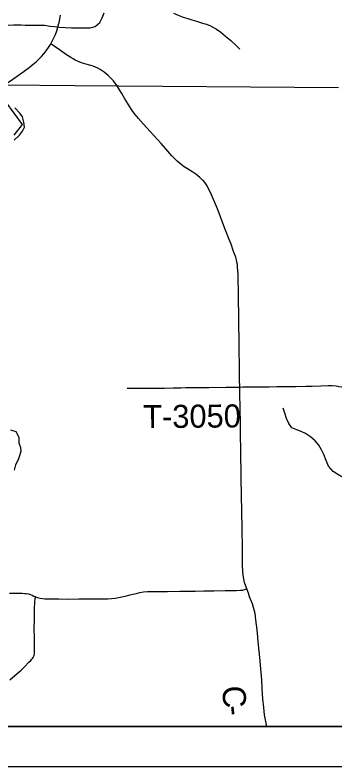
# Model space of a CAD drawing. Extents: x 0 to 34, y 0 to 22.
# Drawn here: x 3.328 to 4.117, y 14.287 to 16.14 of the extents above; entities that cross this region are included whole.
import ezdxf

# ---------------------------------------------------------------- set-up
doc = ezdxf.new("R2010")
doc.units = 0
for name, color, linetype in [('GM_X_County_Road', 7, 'Continuous'), ('GM_X_County_Road_Text', 7, 'Continuous'), ('GM_X_Interchange_Ramps', 7, 'Continuous'), ('GM_X_Section_Text', 7, 'Continuous'), ('GM_X_State_Route', 7, 'Continuous'), ('GM_X_State_Shield', 7, 'Continuous'), ('GM_X_Township_Road', 7, 'Continuous'), ('GM_X_Township_Text', 7, 'Continuous'), ('SH_Data', 7, 'Continuous')]:
    doc.layers.add(name, color=color, linetype=linetype)

msp = doc.modelspace()

# ---------------------------------------------------------------- linework, layer by layer
at = {"layer": 'GM_X_County_Road'}
msp.add_lwpolyline([(3.3022, 15.9674), (3.3093, 15.9728), (3.3228, 15.9822), (3.3508, 16.0019), (3.3633, 16.0111), (3.373, 16.0188), (3.38, 16.0248), (3.3868, 16.0312), (3.3933, 16.0378), (3.3995, 16.0447), (3.4052, 16.052), (3.4106, 16.0596), (3.4156, 16.0674), (3.4164, 16.0689), (3.4201, 16.0755), (3.4242, 16.0838), (3.4279, 16.0923), (3.4312, 16.101), (3.4341, 16.1098), (3.4365, 16.1188), (3.4378, 16.1248), (3.4389, 16.1309), (3.4401, 16.1401)], dxfattribs=at)
at = {"layer": 'GM_X_County_Road_Text'}
for points in [[(3.2957, 16.1168), (3.3124, 16.1151), (3.3242, 16.1155), (3.3435, 16.1156), (3.353, 16.1153), (3.3901, 16.1154), (3.4011, 16.1147), (3.4151, 16.1128), (3.4254, 16.1114), (3.4367, 16.1099), (3.4519, 16.1092), (3.4678, 16.1085), (3.4936, 16.1086), (3.5035, 16.1082), (3.5133, 16.1087), (3.5254, 16.1121), (3.5375, 16.1213), (3.5431, 16.1334), (3.5476, 16.1452)], [(3.7185, 16.1447), (3.7307, 16.1398), (3.7428, 16.1346), (3.7542, 16.1316), (3.7641, 16.1282), (3.7755, 16.1252), (3.7903, 16.12), (3.8001, 16.1173), (3.81, 16.1136), (3.8248, 16.1053), (3.8355, 16.0977), (3.8473, 16.0879), (3.8598, 16.0773), (3.8731, 16.0652), (3.8826, 16.0562)], [(4.1378, 14.9976), (4.1377, 14.9995), (4.124, 15.0077), (4.1122, 15.0152), (4.1011, 15.028), (4.0953, 15.042), (4.0891, 15.0564), (4.0836, 15.0681), (4.0767, 15.0794), (4.0683, 15.0907), (4.0564, 15.1005), (4.0442, 15.1083), (4.0336, 15.1131), (4.0229, 15.1172), (4.0107, 15.1228), (4.003, 15.1334), (3.9973, 15.1454), (3.993, 15.1587), (3.9891, 15.1708)], [(3.3172, 15.1172), (3.3305, 15.1131), (3.3374, 15.0995), (3.3376, 15.0855), (3.3418, 15.0741), (3.3427, 15.0647), (3.3394, 15.0536), (3.3357, 15.0437), (3.3297, 15.0312), (3.3257, 15.0182)]]:
    msp.add_lwpolyline(points, dxfattribs=at)
at = {"layer": 'GM_X_Interchange_Ramps'}
for points in [[(3.6044, 15.2203), (3.6437, 15.2202), (3.678, 15.2203), (3.6967, 15.2204), (3.7184, 15.2209), (3.7371, 15.2215), (3.7496, 15.2216), (3.7813, 15.2216), (3.8059, 15.222), (3.849, 15.2224), (3.8707, 15.2228), (3.882, 15.2231)], [(3.882, 15.2231), (3.8894, 15.2232), (3.9019, 15.2234), (3.9174, 15.2236), (3.936, 15.2238), (3.9547, 15.2239), (3.9733, 15.2241), (3.9982, 15.2243), (4.02, 15.2246), (4.0449, 15.2252), (4.0604, 15.2255), (4.0822, 15.2263), (4.1009, 15.2268), (4.1102, 15.2267), (4.1195, 15.2259), (4.1266, 15.2248), (4.1333, 15.2232), (4.1402, 15.2211)], [(3.3794, 14.7059), (3.3839, 14.7043), (3.3898, 14.7027), (3.3959, 14.7017), (3.402, 14.7011), (3.4174, 14.7007), (3.436, 14.7007), (3.4609, 14.7006), (3.4858, 14.7008), (3.5044, 14.7009), (3.5168, 14.7009), (3.5364, 14.7008), (3.557, 14.7013), (3.5662, 14.7018), (3.5754, 14.7028), (3.5876, 14.7049), (3.5997, 14.7076), (3.6118, 14.7106), (3.6298, 14.7153), (3.636, 14.7166), (3.6452, 14.718), (3.6545, 14.7188), (3.67, 14.7192), (3.6886, 14.7193), (3.704, 14.7193), (3.7348, 14.7196), (3.7502, 14.7199), (3.7719, 14.7202), (3.7936, 14.7205), (3.8184, 14.7209), (3.8464, 14.7212), (3.8744, 14.7216), (3.8837, 14.722), (3.8895, 14.7228), (3.8936, 14.7237), (3.8966, 14.7245), (3.8997, 14.7256)], [(3.3148, 14.7149), (3.3344, 14.7149), (3.3456, 14.7147), (3.3513, 14.7144), (3.3557, 14.7141), (3.3616, 14.7134), (3.3667, 14.7118), (3.3705, 14.7103), (3.3747, 14.7079), (3.3794, 14.7059)], [(3.3151, 14.5014), (3.3339, 14.5169), (3.343, 14.5251), (3.3519, 14.5337), (3.3625, 14.545), (3.367, 14.5493), (3.3691, 14.5515), (3.3712, 14.554), (3.3731, 14.5567), (3.3746, 14.5594), (3.3755, 14.5622), (3.3762, 14.5651), (3.3765, 14.5714), (3.3765, 14.5807), (3.3761, 14.6055), (3.3757, 14.6273), (3.3759, 14.649), (3.3764, 14.68), (3.3768, 14.6893), (3.3771, 14.6955), (3.3776, 14.6987), (3.3782, 14.7018), (3.3794, 14.7059)]]:
    msp.add_lwpolyline(points, dxfattribs=at)
at = {"layer": 'GM_X_State_Route'}
for points in [[(4.1201, 16.507), (4.1149, 16.7255), (3.8667, 16.7261), (3.8624, 16.726), (3.8538, 16.7259), (3.7775, 16.7251), (3.6944, 16.7259), (3.6091, 16.7254), (3.5492, 16.7252), (3.5064, 16.7242), (3.4642, 16.7247), (3.3781, 16.7258), (3.3363, 16.7271), (3.2929, 16.7282), (3.2508, 16.7281), (3.0563, 16.7255), (2.994, 16.7266), (1.8602, 16.7212), (1.8602, 14.3866), (4.1451, 14.3866)], [(3.302, 15.9679), (3.4757, 15.9666), (4.1252, 15.961)], [(3.3259, 15.8442), (3.3468, 15.8704), (3.2842, 15.9538)]]:
    msp.add_lwpolyline(points, dxfattribs=at)
at = {"layer": 'GM_X_State_Shield'}
msp.add_lwpolyline([(3.3265, 15.8313), (3.339, 15.8439), (3.3465, 15.8538), (3.3514, 15.8633), (3.3502, 15.8758), (3.3464, 15.8887), (3.3399, 15.8985), (3.3281, 15.9114)], dxfattribs=at)
at = {"layer": 'GM_X_Township_Road'}
for points in [[(3.5812, 15.9639), (3.5784, 15.9682), (3.5746, 15.9731), (3.5706, 15.9777), (3.5641, 15.9844), (3.5574, 15.9909), (3.5528, 15.9949), (3.5479, 15.9988), (3.5429, 16.0024), (3.5377, 16.0058), (3.5324, 16.0088), (3.5268, 16.0115), (3.5211, 16.0138), (3.5152, 16.0158), (3.5063, 16.0184), (3.4942, 16.0217), (3.4883, 16.0237), (3.4824, 16.026), (3.4767, 16.0287), (3.4712, 16.0317), (3.4659, 16.035), (3.4529, 16.0437), (3.44, 16.0525), (3.427, 16.0613), (3.4245, 16.0631), (3.4164, 16.0689)], [(3.882, 15.2231), (3.8817, 15.242), (3.8816, 15.2669), (3.8814, 15.2793), (3.881, 15.3104), (3.8808, 15.3291), (3.8805, 15.3478), (3.8801, 15.3695), (3.8798, 15.385), (3.8796, 15.4099), (3.8794, 15.4286), (3.8788, 15.4628), (3.8785, 15.4846), (3.8781, 15.5002), (3.8777, 15.5094), (3.8769, 15.5187), (3.8762, 15.5248), (3.8751, 15.5309), (3.8738, 15.5369), (3.8721, 15.5428), (3.867, 15.5575), (3.8606, 15.5751), (3.8563, 15.5867), (3.8473, 15.6099), (3.8404, 15.6273), (3.8336, 15.6447), (3.8269, 15.6621), (3.82, 15.6794), (3.8152, 15.6909), (3.81, 15.7022), (3.8045, 15.7133), (3.8015, 15.7187), (3.7982, 15.7239), (3.7965, 15.7264), (3.7926, 15.7312), (3.7905, 15.7334), (3.7838, 15.7399), (3.7791, 15.7439), (3.7742, 15.7476), (3.7665, 15.7528), (3.7533, 15.761), (3.7454, 15.766), (3.7378, 15.7715), (3.7329, 15.7754), (3.7282, 15.7795), (3.7215, 15.7861), (3.7151, 15.7929), (3.7048, 15.8045), (3.6884, 15.823), (3.6612, 15.8526), (3.6447, 15.8711), (3.6325, 15.8852), (3.6245, 15.8947), (3.6187, 15.902), (3.6152, 15.9071), (3.6068, 15.9202), (3.5988, 15.9335), (3.5912, 15.947), (3.5812, 15.9639)], [(3.8997, 14.7256), (3.894, 14.7411), (3.8919, 14.7502), (3.8904, 14.7595), (3.8895, 14.7688), (3.8891, 14.7843), (3.8891, 14.8247), (3.8881, 14.8743), (3.8854, 14.9983), (3.8845, 15.0697), (3.8843, 15.1038), (3.8839, 15.1286), (3.8829, 15.1751), (3.8823, 15.203), (3.882, 15.2231)], [(3.9491, 14.3866), (3.9481, 14.3907), (3.9455, 14.4028), (3.9435, 14.415), (3.9412, 14.4334), (3.9393, 14.4549), (3.9376, 14.4796), (3.9363, 14.5012), (3.9348, 14.5197), (3.9315, 14.5568), (3.9286, 14.5877), (3.9249, 14.6247), (3.922, 14.6494), (3.9198, 14.6648), (3.9179, 14.674), (3.9162, 14.68), (3.9132, 14.6888), (3.9064, 14.7062), (3.9034, 14.7147), (3.8997, 14.7256)]]:
    msp.add_lwpolyline(points, dxfattribs=at)
at = {"layer": 'SH_Data'}
for points in [[(1.7602, 21.2866), (8.7602, 21.2866), (8.7602, 14.2866), (1.7602, 14.2866)], [(1.8602, 21.1866), (8.6602, 21.1866), (8.6602, 14.3866), (1.8602, 14.3866)]]:
    msp.add_lwpolyline(points, close=True, dxfattribs=at)

# ---------------------------------------------------------------- texts
at = {"layer": 'GM_X_Section_Text'}
for s, rotation, p in [('C', 273.3077, (3.8389, 14.4853)), ('-', 275.7703, (3.8418, 14.4361))]:
    msp.add_text(s, height=0.0568, rotation=rotation, dxfattribs=at).set_placement(p)
at = {"layer": 'GM_X_Township_Text'}
msp.add_text('T-3050', height=0.05682, rotation=0.4648, dxfattribs=at).set_placement((3.6443, 15.1217))

doc.saveas('drawing.dxf')
